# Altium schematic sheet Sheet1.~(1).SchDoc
size A; SheetNumber: 1; SheetTotal: 1; SPICEModelCacheKHWKRCUS: <root> / <DocumentId>KHWKRCUS</DocumentId> / <CacheFrame Number="0"> / <Model Name="nmos" Kind="MDL"> / <Text>*Default N-Channel MOSFET / *Pinout: D,G,S / .MODEL NMOS NMOS()</Text> / </Model> / <Model Name="diode" Kind="MDL"> / <Text>*Default Diode / *Diode Pinout: A,K / .MODEL DIODE D()</Text> / </Model> / </CacheFrame> / </root>
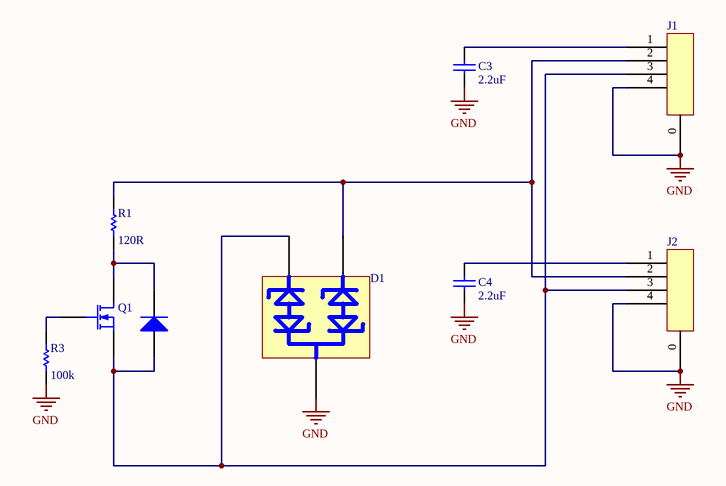
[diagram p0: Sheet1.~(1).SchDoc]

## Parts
C3  2.2uF  [RAD-0.3]
C4  2.2uF  [RAD-0.3]
D1  BRIDGE  (value not drawn)
D?  Diode  [SMC]  (value not drawn)
J1  HEADER  (value not drawn)
J2  HEADER  (value not drawn)
Q1  MOSFET-N  [E3]  (value not drawn)
R1  120R  [AXIAL-0.3]
R3  100k  [AXIAL-0.3]

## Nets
GND: C3.1 C4.1 D1.3 J1.0 J1.4 J2.0 J2.4 R3.1
NetC3_2: C3.2 J1.1
NetC4_2: C4.2 J2.1
NetD1_1: D1.1 J1.2 J2.2 R1.2
NetD1_2: D1.2 D?.1(A) J1.3 J2.3 Q1.3(S)
NetD?_2: D?.2(K) Q1.1(D) R1.1
NetQ1_2: Q1.2(G) R3.2

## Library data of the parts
C3 C4 = Cap: Capacitor
D? = Diode: Default Diode
Q1 = MOSFET-N: N-Channel MOSFET
R1 R3 = Res1: Resistor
